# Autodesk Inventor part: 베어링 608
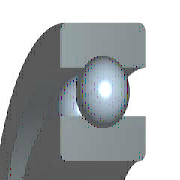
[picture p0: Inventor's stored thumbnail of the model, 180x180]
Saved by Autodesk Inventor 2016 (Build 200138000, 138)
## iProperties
IsCustomPart: 1
Created: 2012-02
Part Number: 베어링 608
Material: 강철, 연강
Description: 깊은 그루브 볼 베어링
Document SubType Name: Modeling
Standard: KS B 2023
Designer: mduedu
Standards Organization: KS
Language: ko-KR
Size Designation: 608 - 8 x 22 x 7
Categories: <MemberInstance><Categories><Category DisplayName="샤프트 부품" InternalName="7f7aeb1f-a693-4053-b835-cee3144e0d98" Mnemonic="SHFT"><Category DisplayName="베어링" Inter
Density: 7.85 g/cm^3
Appearance: 노란색
Mass: 12.145 g
Surface Area: 20.0754 cm^2
Volume: 1.54714 cm^3
Author: mduedu
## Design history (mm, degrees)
sketch "스케치" dims "d0" = 3.64 (= -0.26 x WD + 0.26 x BD)
  geometry: L1 (1.68, 7.5)-(5.32, 7.5); L2 (3.5, 7.5)-(3.5, 5.68); L3 (3.5, 7.5)-(3.5, 9.32); L4 (2.148, 6.282)-(0, 6.282); L5 (0, 4)-(7, 4); L6 (2.148, 8.718)-(0, 8.718); L7 (0, 11)-(7, 11); L8 (7, 4)-(7, 6.282); L9 (4.852, 6.282)-(7, 6.282); L10 (4.852, 8.718)-(7, 8.718); L11 (7, 11)-(7, 8.718); L12 (-1.4, 0)-(8.4, 0) reference; L13 (0, -0.3)-(0, 5.3) reference
  constraints: 22 end point, 4 point on line, 2 collinear, 2 perpendicular, 2 symmetric about line, 1 midpoint, 1 parallel, 14 other
  dimensions: "d9" = 8 diameter of L5 L12 (= WD); "d11" = 22 diameter of L7 L12 (= BD); "d12" = 7 distance between parallel lines of L8 L13 (= KB); "d13" = 12.564 diameter of L9 L12 (= 0.326 x BD + 0.674 x WD)
revolve "본체" stored, may be unused: angle "d6" = 90 deg
revolve "볼" stored, may be unused: angle "d7" = 90 deg
pattern_circular "IDS_ARRAYBALL[SIMPL:T]" dims angle "d3" = 360 deg
body "Solid1"
fillet "모깎기1" dims "d1" = 0.3 (= KRS)
other parameters: "WD" = 8 [user parameter; used in 5 equation terms], "BD" = 22 [user parameter; used in 5 equation terms], "KB" = 7 [user parameter; used in 1 equation term], "KRS" = 0.3 [user parameter; used in 1 equation term], "d4" = 0, "d5" = 0, "d8" = 0, "d14" = 0, "d15" = 0, "BBA" = 0 [user parameter], "BC0" = 1370000 [user parameter], "BC" = 3250000 [user parameter], "BR" = 11 (= 0.5 x BD) [user parameter], "WR" = 4 (= 0.5 x WD) [user parameter]
